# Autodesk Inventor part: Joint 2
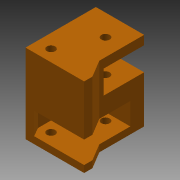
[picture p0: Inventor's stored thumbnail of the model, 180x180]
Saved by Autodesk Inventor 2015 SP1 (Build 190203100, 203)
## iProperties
Created: 2008-11
Part Number: Joint 2
Document SubType Name: Modeling
Designer: dwoollam
Density: 7.85 g/cm^3
Material: Steel
Appearance: Orange
Mass: 569817 g
Surface Area: 19137.8 cm^2
Volume: 72588.2 cm^3
Dwg_Category: Clearance_Mewp
INSTALLATION: False
CIVIL_WORK: False
EARTHING: False
MOUNTING: False
Author: dwoollam
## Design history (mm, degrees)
sketch "Sketch1"
  geometry: L1 (-212.5, 255)-(-212.5, -255); L2 (-212.5, -255)-(212.5, -255); L3 (212.5, -255)-(212.5, -195); L4 (212.5, -195)-(137.5, -70); L5 (137.5, -70)-(137.5, 255); L6 (137.5, 255)-(-212.5, 255); C1 r 30 at (12.5, 100); C2 r 30 at (-112.5, -170); 3 further points
  constraints: 12 end point, 3 parallel, 2 centre point, 2 midpoint, 1 equal radius, 1 horizontal alignment, 1 perpendicular, 1 vertical, 1 vertical alignment
  dimensions: "d0" = 425 distance of L1.end L2.end; "d1" = 510 distance of L1.start L1.end; "d2" = 350 distance of L5.end L1.start; "d3" = 60 distance of L2.end L3.end; "d4" = 325 distance of L4.end L5.end; "d5" = 85 distance from line of L2 C2.centre; "d6" = 100 distance from line of L1 C2.centre; "d7" = 60 diameter of C2; "d9" = 225 distance from line of L1 C1.centre; "d10" = 155 distance from line of L6 C1.centre
extrude "Main Body" new body sketch "Sketch1" stored distance "d11" = 575; taper "d12" = 0 deg
workplane "Work Plane1"
workplane "Work Plane2"
sketch "Sketch2"
  geometry: L1 (212.5, -255)-(-212.5, -255) reference; L2 (212.5, 255)-(212.5, -255) reference; L3 (187.5, -190.096)-(187.5, 155); L4 (187.5, 155)-(-212.5, 155); L5 (-212.5, 155)-(-212.5, -255); L6 (-212.5, -255)-(150.028, -255); L7 (150.028, -255)-(187.5, -190.096); C1 r 30 at (112.5, -170) reference; 1 further point
  constraints: 10 end point, 3 parallel, 2 coincident, 1 perpendicular
  dimensions: "d15" = 150 deg angle of L7 L3; "d16" = 75 distance from line of L3 C1.centre; "d17" = 75 distance from line of L7 C1.centre (= d16); "d18" = 325 distance from line of L4 C1.centre
extrude "Subtraction_1" cut sketch "Sketch2" distance "d19" = 160; taper "d20" = 0 deg
sketch "Sketch3"
  geometry: L1 (-212.5, 255)-(137.5, 255) reference; L2 (137.5, 255)-(-212.5, 255) reference; L3 (-212.5, -255)-(-212.5, 255) reference; L4 (-212.5, 255)-(-212.5, -255) reference; L5 (-110, 100)-(137.5, 100); L6 (-105.826, 131.705)-(-72.789, 255); L7 (-72.789, 255)-(137.5, 255); L8 (137.5, 255)-(137.5, -38.768); L9 (-2.429, -21.587)-(137.5, -38.768); C1 r 30 at (12.5, 100) reference; C2 r 30 at (12.5, 100) reference; A1 r 122.5 centre (12.5, 100) between (-105.826, 131.705) and (12.5, -22.5); 3 further points
  constraints: 10 end point, 4 point on circle, 3 coincident, 2 point on line, 2 tangent, 1 centre point, 1 collinear, 1 horizontal, 1 horizontal alignment, 1 parallel
  dimensions: "d21" = 245 diameter of A1; "d22" = 7 deg angle of L5 L9; "d23" = 75 deg angle of L5 L6
extrude "Subtraction 2" cut sketch "Sketch3" distance "d24" = 170; taper "d25" = 0 deg
body "Solid1"
node "Projected Loop1"
node "Projected Loop2"
node "Projected Loop3"
other parameters: "d13" = -65
